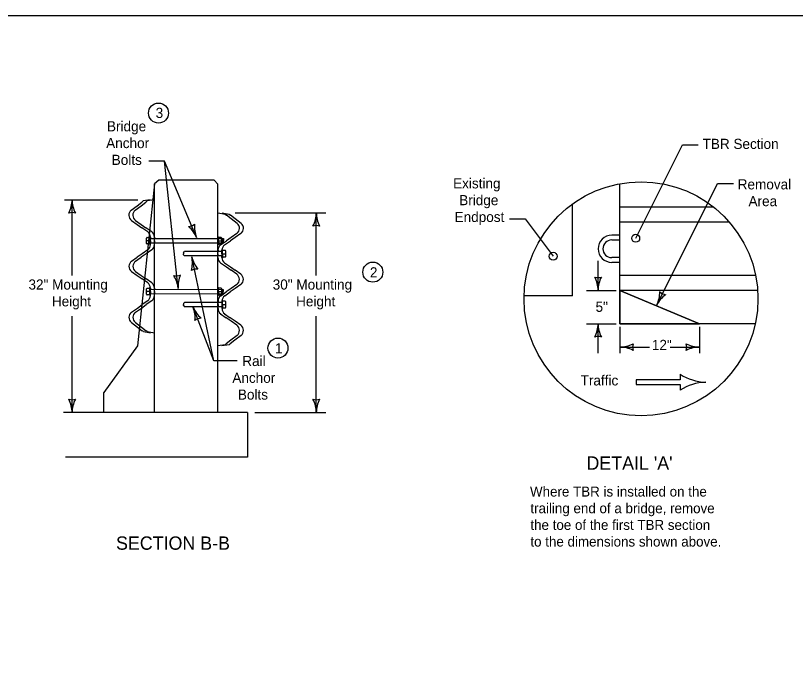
# Model space of a CAD drawing. Extents: x 10028 to 81668, y 3581 to 11018.
# Drawn here: x 21774 to 22944, y 8962 to 9944 of the extents above; entities that cross this region are included whole.
import ezdxf

# ---------------------------------------------------------------- set-up
doc = ezdxf.new("R2010")
doc.units = 0
for name, color, linetype in [('conPaving', 7, 'Continuous'), ('dsnCellsNorthArrow', 7, 'Continuous'), ('dsnTextTabulation', 7, 'Continuous'), ('Level 41', 7, 'Continuous'), ('Level 9', 7, 'Continuous'), ('SheetBorder', 7, 'Continuous')]:
    doc.layers.add(name, color=color, linetype=linetype)

msp = doc.modelspace()

# ---------------------------------------------------------------- linework, layer by layer
at = {"layer": 'conPaving'}
for p, q in [((22084.2, 9609.4), (22083.7, 9603)), ((22084.8, 9609.4), (22084.3, 9603)), ((22085.3, 9609.4), (22084.8, 9603)), ((22085.9, 9609.4), (22085.4, 9603)), ((22084.2, 9533.3), (22083.7, 9526.8)), ((22084.7, 9533.3), (22084.2, 9526.8)), ((22085.3, 9533.3), (22084.8, 9526.8)), ((22085.8, 9533.3), (22085.3, 9526.8))]:
    msp.add_line(p, q, dxfattribs=at)
at = {"layer": 'dsnCellsNorthArrow'}
for p, q in [((21982.4, 9691.6), (21957.2, 9448.6)), ((21988.9, 9697.3), (21982.4, 9691.6)), ((21982.4, 9348.6), (21982.4, 9691.6)), ((22072, 9697.3), (21988.9, 9697.3)), ((22077.8, 9691.3), (22072, 9697.3)), ((22077.8, 9348.6), (22077.8, 9691.3)), ((21957.2, 9448.6), (21906.6, 9378.6)), ((21906.6, 9348.6), (21906.6, 9378.6))]:
    msp.add_line(p, q, dxfattribs=at)
at = {"layer": 'dsnTextTabulation'}
for p, q in [((22704.6, 9610), (22775, 9750.1)), ((22775, 9750.1), (22798.6, 9750.1)), ((21997.6, 9725.6), (21974, 9725.6)), ((22045.8, 9610.9), (21997.6, 9725.6)), ((22018.3, 9534.5), (21997.6, 9725.6)), ((22680.7, 9481.8), (22680.7, 9691.8)), ((22736.1, 9509.8), (22827.6, 9692)), ((22827.6, 9692), (22851.2, 9692)), ((21847.8, 9667.8), (21957.7, 9667.8)), ((21965.7, 9665.9), (21963.7, 9664.3)), ((21976.3, 9667.8), (21965.7, 9665.9)), ((21971.7, 9665.9), (21969.7, 9664.3)), ((21982.3, 9667.8), (21971.7, 9665.9)), ((21858.9, 9554), (21858.9, 9661.9)), ((21947.8, 9651.9), (21956.6, 9658.8)), ((21953.8, 9651.9), (21962.6, 9658.8)), ((21956.6, 9658.8), (21963.7, 9664.3)), ((21962.6, 9658.8), (21969.7, 9664.3)), ((22821.9, 9656.6), (22680.7, 9656.6)), ((22078, 9648.2), (22088.6, 9646.3)), ((22084, 9648.2), (22094.6, 9646.3)), ((22088.6, 9646.3), (22090.7, 9644.7)), ((22097.7, 9639.2), (22090.7, 9644.7)), ((22094.6, 9646.3), (22096.7, 9644.7)), ((22103.7, 9639.2), (22096.7, 9644.7)), ((22103.8, 9648.2), (22239.8, 9648.2)), ((22225.4, 9554), (22225.4, 9648.2)), ((21948.1, 9636.8), (21956.6, 9630.8)), ((21954.1, 9636.8), (21962.6, 9630.8)), ((21956.6, 9630.8), (21963.8, 9625.6)), ((21962.6, 9630.8), (21969.8, 9625.6)), ((22106.5, 9632.3), (22097.7, 9639.2)), ((22112.5, 9632.3), (22103.7, 9639.2)), ((22515.2, 9639.1), (22538.8, 9639.1)), ((22538.8, 9639.1), (22580.8, 9583)), ((22845.3, 9634.1), (22680.7, 9634.1)), ((21972.5, 9619.5), (21963.8, 9625.6)), ((21978.5, 9619.5), (21969.8, 9625.6)), ((21976.5, 9611.8), (21976.5, 9610.1)), ((21976.5, 9606.2), (21976.5, 9610.1)), ((21982.5, 9611.8), (21982.5, 9610.1)), ((21982.5, 9606.2), (21982.5, 9610.1)), ((22097.8, 9611.2), (22090.5, 9606.1)), ((22103.8, 9611.2), (22096.5, 9606.1)), ((22106.2, 9617.2), (22097.8, 9611.2)), ((22112.2, 9617.2), (22103.8, 9611.2)), ((21976.5, 9606.3), (21976.5, 9602.5)), ((21976.5, 9600.5), (21976.5, 9602.5)), ((21982.5, 9606.3), (21982.5, 9602.5)), ((21982.5, 9600.5), (21982.5, 9602.5)), ((22081.8, 9599.9), (22090.5, 9606.1)), ((22087.8, 9599.9), (22096.5, 9606.1)), ((21963.9, 9586.6), (21956.7, 9581.4)), ((21969.9, 9586.6), (21962.7, 9581.4)), ((21972.6, 9592.8), (21963.9, 9586.6)), ((21978.6, 9592.8), (21969.9, 9586.6)), ((22077.8, 9586.6), (22077.9, 9590.5)), ((22077.8, 9586.8), (22077.8, 9583)), ((22077.9, 9592.3), (22077.9, 9590.5)), ((22083.8, 9586.6), (22083.9, 9590.5)), ((22083.8, 9586.8), (22083.8, 9583)), ((22083.9, 9592.3), (22083.9, 9590.5)), ((21948.3, 9575.4), (21956.7, 9581.4)), ((21954.3, 9575.4), (21962.7, 9581.4)), ((22071.8, 9426.2), (22038.5, 9582.3)), ((22077.8, 9581), (22077.8, 9583)), ((22081.8, 9573.3), (22090.4, 9567.1)), ((22083.8, 9581), (22083.8, 9583)), ((22087.8, 9573.3), (22096.4, 9567.1)), ((22648.2, 9531.8), (22648.2, 9576.1)), ((21948, 9560.3), (21956.8, 9554.1)), ((21954, 9560.3), (21962.8, 9554.1)), ((22090.4, 9567.1), (22097.6, 9561.9)), ((22096.4, 9567.1), (22103.6, 9561.9)), ((22106, 9555.9), (22097.6, 9561.9)), ((22112, 9555.9), (22103.6, 9561.9)), ((21956.8, 9554.1), (21964, 9548.9)), ((21962.8, 9554.1), (21970, 9548.9)), ((21972.4, 9543), (21964, 9548.9)), ((21978.4, 9543), (21970, 9548.9)), ((22884.6, 9554.2), (22680.7, 9554.2)), ((22106.3, 9540.7), (22097.5, 9534.5)), ((22112.3, 9540.7), (22103.5, 9534.5)), ((21976.4, 9535.3), (21976.4, 9533.7)), ((21976.4, 9530), (21976.4, 9533.7)), ((21976.4, 9530), (21976.4, 9526.2)), ((21976.4, 9524), (21976.4, 9526.2)), ((21982.4, 9535.3), (21982.4, 9533.7)), ((21982.4, 9530), (21982.4, 9533.7)), ((21982.4, 9530), (21982.4, 9526.2)), ((21982.4, 9524), (21982.4, 9526.2)), ((22081.9, 9523.4), (22090.3, 9529.4)), ((22087.9, 9523.4), (22096.3, 9529.4)), ((22097.5, 9534.5), (22090.3, 9529.4)), ((22103.5, 9534.5), (22096.3, 9529.4)), ((22630.9, 9531.8), (22675.2, 9531.8)), ((22887.7, 9531.8), (22680.7, 9531.8)), ((21972.5, 9516.3), (21964.1, 9510.4)), ((21978.5, 9516.3), (21970.1, 9510.4)), ((22077.9, 9515.8), (22077.9, 9514.2)), ((22077.9, 9510.4), (22077.9, 9514.2)), ((22083.9, 9515.8), (22083.9, 9514.2)), ((22083.9, 9510.4), (22083.9, 9514.2)), ((21948.2, 9498.9), (21956.9, 9505.2)), ((21954.2, 9498.9), (21962.9, 9505.2)), ((21956.9, 9505.2), (21964.1, 9510.4)), ((21962.9, 9505.2), (21970.1, 9510.4)), ((22071.8, 9426.2), (22040.4, 9506.8)), ((22077.9, 9510.4), (22077.9, 9506.7)), ((22077.9, 9504.5), (22077.9, 9506.7)), ((22083.9, 9510.4), (22083.9, 9506.7)), ((22083.9, 9504.5), (22083.9, 9506.7)), ((21858.9, 9348.5), (21858.9, 9493)), ((22081.8, 9496.8), (22090.2, 9490.8)), ((22087.8, 9496.8), (22096.2, 9490.8)), ((22097.4, 9485.6), (22090.2, 9490.8)), ((22103.4, 9485.6), (22096.2, 9490.8)), ((22225.4, 9348.5), (22225.4, 9493)), ((21947.9, 9483.8), (21957.1, 9476.7)), ((21953.9, 9483.8), (21963.1, 9476.7)), ((22106.1, 9479.4), (22097.4, 9485.6)), ((22112.1, 9479.4), (22103.4, 9485.6)), ((22630.9, 9481.8), (22675.2, 9481.8)), ((22648.2, 9437.5), (22648.2, 9481.8)), ((22884.1, 9481.8), (22680.7, 9481.8)), ((21957.1, 9476.7), (21964.1, 9471.3)), ((21963.1, 9476.7), (21970.1, 9471.3)), ((21966, 9469.9), (21964.1, 9471.3)), ((21966, 9469.9), (21976.6, 9468.1)), ((21972, 9469.9), (21970.1, 9471.3)), ((21972, 9469.9), (21982.6, 9468.1)), ((22680.7, 9476.9), (22680.7, 9437.7)), ((22800.5, 9476.9), (22800.5, 9437.7)), ((22097.2, 9457.2), (22090.2, 9451.8)), ((22103.2, 9457.2), (22096.2, 9451.8)), ((22106.4, 9464.3), (22097.2, 9457.2)), ((22112.4, 9464.3), (22103.2, 9457.2)), ((22088.4, 9450.3), (22077.8, 9448.5)), ((22094.4, 9450.3), (22083.8, 9448.5)), ((22088.4, 9450.3), (22090.2, 9451.8)), ((22094.4, 9450.3), (22096.2, 9451.8)), ((22680.7, 9446.8), (22725.1, 9446.8)), ((22756.1, 9446.8), (22800.5, 9446.8)), ((22106.7, 9426.2), (22071.8, 9426.2)), ((22133.1, 9348.5), (22239.8, 9348.5))]:
    msp.add_line(p, q, dxfattribs=at)
for centre in [(21988.6, 9797.8), (22310.2, 9559.2), (22167.9, 9445.3)]:
    msp.add_circle(centre, 15, dxfattribs=at)
for centre, radius, start, end in [((21816.4, 9667.8), 42.5, 331.9275, 360), ((21901.4, 9667.8), 42.5, 180, 208.0725), ((21858.9, 9632.1), 16.4, 72.2666, 107.7334), ((22182.9, 9648.2), 42.5, 331.9275, 360), ((22267.9, 9648.2), 42.5, 180, 208.0725), ((22032.3, 9643.9), 16.4, 274.4291, 309.8958), ((22085.1, 9627), 42.5, 174.09, 202.1625), ((22006.4, 9594.9), 42.5, 22.1625, 50.235), ((22225.4, 9612.6), 16.4, 72.2666, 107.7334), ((21997, 9573), 42.5, 344.5421, 12.6146), ((22080, 9591.5), 42.5, 192.6146, 220.6871), ((22046.3, 9547.5), 16.4, 84.8812, 120.3479), ((22014.8, 9569.9), 16.4, 257.8046, 293.2713), ((21976, 9530.4), 42.5, 5.538, 33.6104), ((22060.6, 9538.6), 42.5, 157.4655, 185.538), ((22648.2, 9567.4), 16.4, 252.2666, 287.7334), ((22605.7, 9531.8), 42.5, 0, 28.0725), ((22648.2, 9567.4), 16.4, 252.2666, 287.7334), ((22605.7, 9531.8), 42.5, 0, 28.0725), ((22690.7, 9531.8), 42.5, 151.9275, 180), ((22690.7, 9531.8), 42.5, 151.9275, 180), ((22698.2, 9529), 42.5, 333.1429, 1.2154), ((22774, 9490.6), 42.5, 125.0704, 153.1429), ((22752.2, 9541.5), 16.4, 225.4095, 260.8762), ((22001, 9491), 42.5, 353.7829, 21.8554), ((22079.9, 9522.7), 42.5, 201.8554, 229.9279), ((22053.7, 9473.8), 16.4, 94.122, 129.5887), ((22605.7, 9481.8), 42.5, 331.9275, 0), ((22605.7, 9481.8), 42.5, 331.9275, 0), ((22690.7, 9481.8), 42.5, 180, 208.0725), ((22690.7, 9481.8), 42.5, 180, 208.0725), ((22648.2, 9446.2), 16.4, 72.2666, 107.7334), ((22648.2, 9446.2), 16.4, 72.2666, 107.7334), ((22680.7, 9489.3), 42.5, 270, 298.0725), ((22680.7, 9489.3), 42.5, 270, 298.0725), ((22680.7, 9404.3), 42.5, 61.9275, 90), ((22680.7, 9404.3), 42.5, 61.9275, 90), ((22716.3, 9446.8), 16.4, 162.2666, 197.7334), ((22716.3, 9446.8), 16.4, 162.2666, 197.7334), ((22764.8, 9446.8), 16.4, 342.2667, 17.7334), ((22800.5, 9489.3), 42.5, 241.9275, 270), ((22764.8, 9446.8), 16.4, 342.2667, 17.7334), ((22800.5, 9489.3), 42.5, 241.9275, 270), ((22800.5, 9404.3), 42.5, 90, 118.0725), ((22800.5, 9404.3), 42.5, 90, 118.0725), ((21858.9, 9384.2), 16.4, 252.2666, 287.7333), ((21816.4, 9348.5), 42.5, 360, 28.0725), ((21901.4, 9348.5), 42.5, 151.9275, 180), ((22225.4, 9384.2), 16.4, 252.2666, 287.7333), ((22182.9, 9348.5), 42.5, 360, 28.0725), ((22267.9, 9348.5), 42.5, 151.9275, 180)]:
    msp.add_arc(centre, radius, start, end, dxfattribs=at)
for centre, major_axis, start_param, end_param in [((21953.6, 9644.5), (9.48, 0.02), 2.229659, 4.096128), ((21959.6, 9644.5), (9.48, 0.02), 2.229659, 4.096128), ((22100.7, 9624.9), (-9.48, 0.02), 2.187057, 4.053527), ((22106.7, 9624.9), (-9.48, 0.02), 2.187057, 4.053527), ((21967, 9611.8), (9.48, 0.02), 0, 0.954538), ((21973, 9611.8), (9.48, 0.02), 0, 0.954538), ((21967, 9600.5), (-9.48, -0.02), 2.187055, 3.141593), ((21973, 9600.5), (-9.48, -0.02), 2.187055, 3.141593), ((22087.3, 9592.3), (-9.48, 0.02), 5.328647, 6.283185), ((22093.3, 9592.3), (-9.48, 0.02), 5.328647, 6.283185), ((21953.8, 9567.8), (-9.48, -0.02), 5.32865, 7.195119), ((21959.8, 9567.8), (-9.48, -0.02), 5.32865, 7.195119), ((22087.3, 9580.9), (9.48, -0.02), 3.141593, 4.096131), ((22093.3, 9580.9), (9.48, -0.02), 3.141593, 4.096131), ((22100.5, 9548.2), (9.48, -0.02), 5.371251, 7.237721), ((22106.5, 9548.2), (9.48, -0.02), 5.371251, 7.237721), ((21966.9, 9535.3), (9.48, 0.02), 0, 0.954538), ((21972.9, 9535.3), (9.48, 0.02), 0, 0.954538), ((21966.9, 9524), (-9.48, -0.02), 2.187055, 3.141593), ((21972.9, 9524), (-9.48, -0.02), 2.187055, 3.141593), ((22087.4, 9515.8), (-9.48, 0.02), 5.328647, 6.283185), ((22093.4, 9515.8), (-9.48, 0.02), 5.328647, 6.283185), ((22087.4, 9504.4), (9.48, -0.02), 3.141593, 4.096131), ((22093.4, 9504.4), (9.48, -0.02), 3.141593, 4.096131), ((21953.7, 9491.3), (-9.48, -0.02), 5.32865, 7.195119), ((21959.7, 9491.3), (-9.48, -0.02), 5.32865, 7.195119), ((22100.6, 9471.7), (9.48, -0.02), 5.371251, 7.237721), ((22106.6, 9471.7), (9.48, -0.02), 5.371251, 7.237721)]:
    msp.add_ellipse(centre, major_axis=major_axis, ratio=0.994906, start_param=start_param, end_param=end_param, dxfattribs=at)
at = {"layer": 'Level 41'}
for p, q in [((22680.7, 9614.5), (22668.7, 9614.5)), ((22680.7, 9607.3), (22668.7, 9607.3)), ((22680.7, 9581), (22668.7, 9581)), ((22680.7, 9573.8), (22668.7, 9573.8))]:
    msp.add_line(p, q, dxfattribs=at)
for radius in [20.4, 13.2]:
    msp.add_arc((22668.7, 9594.2), radius, 90, 270, dxfattribs=at)
at = {"layer": 'Level 9'}
for p, q in [((22609.8, 9523.4), (22609.8, 9661.5)), ((21970.8, 9605.4), (21970.8, 9610.3)), ((21971.7, 9611.2), (21975.6, 9611.2)), ((21975.6, 9606.3), (21975.6, 9612.4)), ((21976.5, 9612.4), (21975.6, 9612.4)), ((21975.6, 9601.4), (21975.6, 9611.2)), ((21976.5, 9600.2), (21976.5, 9612.4)), ((21976.5, 9606.3), (21976.5, 9609.5)), ((21976.5, 9609.5), (22085.9, 9609.4)), ((22077.8, 9600.1), (22077.8, 9612.3)), ((22077.8, 9612.3), (22078.7, 9612.3)), ((22077.8, 9606.2), (22077.8, 9609.4)), ((22078.7, 9606.2), (22078.7, 9612.3)), ((22078.7, 9601.3), (22078.7, 9611.1)), ((22082.5, 9611.1), (22078.7, 9611.1)), ((22083.5, 9605.3), (22083.5, 9610.2)), ((21970.8, 9602.3), (21970.8, 9605.4)), ((21975.6, 9606.3), (21971.7, 9606.3)), ((21975.6, 9601.4), (21971.7, 9601.4)), ((21975.6, 9606.3), (21975.6, 9600.2)), ((21975.6, 9600.2), (21976.5, 9600.2)), ((21976.5, 9603.1), (22085.4, 9603)), ((22078.7, 9600.1), (22077.8, 9600.1)), ((22078.7, 9606.2), (22078.7, 9600.1)), ((22078.7, 9606.2), (22082.5, 9606.2)), ((22078.7, 9601.3), (22082.5, 9601.4)), ((22083.5, 9602.2), (22083.5, 9605.3)), ((22026.2, 9588.3), (22027.4, 9590)), ((22026.2, 9588.3), (22026.2, 9586.7)), ((22026.2, 9585.1), (22026.2, 9586.7)), ((22026.2, 9585.1), (22027.4, 9583.5)), ((22083.8, 9590), (22027.4, 9590)), ((22083.9, 9583.5), (22027.4, 9583.5)), ((22083.9, 9580.7), (22083.8, 9592.8)), ((22083.8, 9592.8), (22084.7, 9592.8)), ((22083.8, 9586.8), (22083.8, 9590)), ((22084.7, 9586.8), (22084.7, 9592.8)), ((22084.8, 9581.9), (22084.7, 9591.6)), ((22088.6, 9591.6), (22084.7, 9591.6)), ((22084.7, 9586.8), (22084.8, 9580.7)), ((22084.7, 9586.8), (22088.6, 9586.8)), ((22089.5, 9585.9), (22089.5, 9590.8)), ((22089.6, 9582.8), (22089.5, 9585.9)), ((22084.8, 9580.7), (22083.9, 9580.7)), ((22084.8, 9581.9), (22088.6, 9581.9)), ((21970.7, 9529.3), (21970.7, 9534.1)), ((21970.7, 9526.1), (21970.7, 9529.3)), ((21971.7, 9535), (21975.5, 9535)), ((21975.5, 9530.1), (21971.7, 9530.1)), ((21975.5, 9525.3), (21971.7, 9525.3)), ((21975.5, 9530.1), (21975.5, 9536.2)), ((21976.4, 9536.2), (21975.5, 9536.2)), ((21975.5, 9525.3), (21975.5, 9535)), ((21975.5, 9530.1), (21975.5, 9524.1)), ((21976.4, 9524.1), (21976.4, 9536.2)), ((21976.4, 9530.1), (21976.4, 9533.4)), ((21976.4, 9533.4), (22085.8, 9533.3)), ((21976.4, 9526.9), (22085.3, 9526.8)), ((22077.8, 9524), (22077.8, 9536.1)), ((22077.8, 9536.1), (22078.7, 9536.1)), ((22077.8, 9530), (22077.8, 9533.3)), ((22078.7, 9530), (22078.7, 9536.1)), ((22078.7, 9525.2), (22078.7, 9534.9)), ((22082.5, 9534.9), (22078.7, 9534.9)), ((22078.7, 9530), (22078.7, 9524)), ((22078.7, 9530), (22082.5, 9530)), ((22078.7, 9525.2), (22082.5, 9525.2)), ((22083.5, 9529.2), (22083.5, 9534)), ((22083.5, 9526), (22083.5, 9529.2)), ((21975.5, 9524.1), (21976.4, 9524.1)), ((22026.3, 9512.2), (22027.5, 9513.8)), ((22083.9, 9513.8), (22027.5, 9513.8)), ((22078.7, 9524), (22077.8, 9524)), ((22083.9, 9504.5), (22083.9, 9516.7)), ((22083.9, 9516.7), (22084.8, 9516.7)), ((22083.9, 9510.6), (22083.9, 9513.8)), ((22084.8, 9510.6), (22084.8, 9516.7)), ((22088.7, 9515.5), (22084.8, 9515.4)), ((22084.8, 9505.7), (22084.8, 9515.4)), ((22089.6, 9509.7), (22089.6, 9514.6)), ((22609.8, 9523.4), (22537.1, 9523.4)), ((22026.3, 9512.2), (22026.3, 9510.5)), ((22026.3, 9508.9), (22026.3, 9510.5)), ((22026.3, 9508.9), (22027.5, 9507.3)), ((22083.9, 9507.3), (22027.5, 9507.3)), ((22084.8, 9504.5), (22083.9, 9504.5)), ((22084.8, 9510.6), (22084.8, 9504.5)), ((22084.8, 9510.6), (22088.7, 9510.6)), ((22084.8, 9505.7), (22088.7, 9505.7)), ((22089.6, 9506.6), (22089.6, 9509.7)), ((22771.3, 9397.6), (22705.3, 9397.6)), ((22705.3, 9397.6), (22705.3, 9390.4)), ((22771.3, 9406), (22771.3, 9397.6)), ((22705.3, 9390.4), (22771.3, 9390.4)), ((22771.3, 9390.4), (22771.3, 9382)), ((22809.6, 9394), (22809.6, 9394)), ((22122, 9348.5), (21846.1, 9348.5)), ((22122, 9348.5), (22122, 9281.5)), ((22122, 9281.5), (21849, 9281.5))]:
    msp.add_line(p, q, dxfattribs=at)
msp.add_lwpolyline([(22680.7, 9481.8), (22800.5, 9481.8), (22680.7, 9531.8), (22680.7, 9481.8)], dxfattribs=at)
msp.add_lwpolyline([(22680.7, 9531.8), (22800.5, 9481.8), (22680.7, 9481.8)], close=True, dxfattribs=at)
for centre, radius in [((22712.6, 9519.2), 175.5), ((22704.6, 9610), 5.96), ((22580.8, 9583), 5.96)]:
    msp.add_circle(centre, radius, dxfattribs=at)
for centre, start, end in [((22812.8, 9471.3), 237.618, 267.648), ((22812.8, 9316.7), 92.352, 122.382)]:
    msp.add_arc(centre, 77.4, start, end, dxfattribs=at)
for centre, major_axis, start_param, end_param in [((21971.7, 9610.3), (-0.96, 0.001), 4.712389, 6.283185), ((21971.7, 9607.2), (-0.96, 0.001), 0, 1.570796), ((22082.5, 9610.2), (-0.96, -0.001), 3.141593, 4.712389), ((22082.5, 9607.1), (-0.96, -0.001), 1.570796, 3.141593), ((21971.7, 9605.4), (-0.96, 0.001), 4.712389, 6.283185), ((21971.7, 9602.3), (-0.96, 0.001), 6.283185, 7.853982), ((22082.5, 9605.3), (-0.96, -0.001), 3.141593, 4.712389), ((22082.5, 9602.2), (-0.96, -0.001), 1.570796, 3.141593), ((22088.6, 9590.8), (-0.96, -0.001), 3.141593, 4.712389), ((22088.6, 9587.6), (-0.96, -0.001), 1.570796, 3.141593), ((22088.6, 9585.9), (-0.96, -0.001), 3.141593, 4.712389), ((22088.6, 9582.8), (-0.96, -0.001), 1.570796, 3.141593), ((21971.7, 9534.1), (-0.96, 0.001), 4.712389, 6.283185), ((21971.7, 9531), (-0.96, 0.001), 0, 1.570796), ((21971.7, 9529.3), (-0.96, 0.001), 4.712389, 6.283185), ((21971.7, 9526.1), (-0.96, 0.001), 6.283185, 7.853982), ((22082.5, 9534), (-0.96, -0.001), 3.141593, 4.712389), ((22082.5, 9530.9), (-0.96, -0.001), 1.570796, 3.141593), ((22082.5, 9529.2), (-0.96, -0.001), 3.141593, 4.712389), ((22082.5, 9526), (-0.96, -0.001), 1.570796, 3.141593), ((22088.7, 9514.6), (-0.96, -0.001), 3.141593, 4.712389), ((22088.7, 9511.5), (-0.96, -0.001), 1.570796, 3.141593), ((22088.7, 9509.7), (-0.96, -0.001), 3.141593, 4.712389), ((22088.7, 9506.6), (-0.96, -0.001), 1.570796, 3.141593)]:
    msp.add_ellipse(centre, major_axis=major_axis, ratio=0.899999, start_param=start_param, end_param=end_param, dxfattribs=at)
at = {"layer": 'SheetBorder'}
msp.add_lwpolyline([(20932.5, 9944), (24067.5, 9944), (24067.5, 7924), (20932.5, 7924)], close=True, dxfattribs=at)

# ---------------------------------------------------------------- texts
at = {"layer": 'dsnCellsNorthArrow'}
for s, height, p in [('Bridge', 15.2, (21911.3, 9770.4)), ('Anchor', 15.2, (21910.1, 9745.2)), ('TBR Section', 15.2, (22805, 9744)), ('Bolts', 15.2, (21918.4, 9720)), ('Existing', 15.2, (22430.6, 9684.8)), ('Removal', 15.2, (22857.7, 9683.3)), ('Bridge', 15.2, (22439.8, 9659.6)), ('Area', 15.2, (22873.9, 9658.1)), ('Endpost', 15.2, (22432.9, 9634.4)), ('32" Mounting', 15.2, (21793.5, 9533)), ('30" Mounting', 15.2, (22160, 9533)), ('Height', 15.2, (21828.6, 9507.8)), ('Height', 15.2, (22195.1, 9507.8)), ('5"', 15.2, (22644.4, 9499.6)), ('12"', 15.2, (22728.9, 9442.4)), ('Rail', 15.2, (22114.3, 9418.3)), ('Anchor', 15.2, (22099.4, 9393.1)), ('Traffic', 15.2, (22622, 9389.2)), ('Bolts', 15.2, (22107.7, 9367.9)), ("DETAIL 'A'", 20, (22630.8, 9262.8)), ('SECTION B-B', 20, (21924.9, 9142.7))]:
    msp.add_text(s, height=height, dxfattribs=at).set_placement(p)
at = {"layer": 'dsnTextTabulation'}
for s, p in [('3', (21984.3, 9790.5)), ('2', (22305.8, 9551.3)), ('1', (22163.5, 9437.4))]:
    msp.add_text(s, height=15.2, dxfattribs=at).set_placement(p)
at = {"layer": 'Level 9'}
for s, p in [('Where TBR is installed on the ', (22546, 9222.5)), ('trailing end of a bridge, remove ', (22546.6, 9197.5)), ('the toe of the first TBR section ', (22546.6, 9172.5)), ('to the dimensions shown above.', (22546.6, 9147.5))]:
    msp.add_text(s, height=15, dxfattribs=at).set_placement(p)

doc.saveas('drawing.dxf')
